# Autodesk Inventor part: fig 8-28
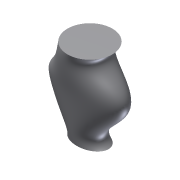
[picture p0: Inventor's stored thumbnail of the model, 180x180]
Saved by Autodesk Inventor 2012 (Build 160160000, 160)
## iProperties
Shininess: 64.0
Length Units: 11269
Angle Units: 11279
Time Units: 11290
Mass Units: 11283
Length Display Precision: 3
Angle Display Precision: 2
Compacted: True
Part Number: fig 8-28
Document SubType Name: Modeling
Created: 2002-12
Designer: deepak
Density: 1 g/cm^3
Material: Default
Density: 0.0
Volumn: 0.0
Area: 0.0
PropertySet Name: Model Information
Control State: 0
Master: False
Checked Out: False
Author: deepak
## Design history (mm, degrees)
sketch "Sketch1"
  geometry: 2 further points; 1 other entity
  constraints: 1 coincident, 3 other
workplane "Work Plane1"
workplane "Work Plane2"
sketch "Sketch3"
  geometry: C1 r 60 at (0, 0); 1 further point
  constraints: 1 centre point, 1 coincident, 1 other
sketch "Sketch4"
  geometry: 8 further points
  constraints: 8 other
sketch "Sketch5"
  geometry: 6 further points
  constraints: 6 other
sketch "Sketch6"
  geometry: 6 further points
  constraints: 6 other
  dimensions: "d20" = 35 distance of point (0, 0) point (-35, 0); "d21" = 0 vertical distance of point (0, 0) point (-35, 0); "d22" = 225 vertical distance of point (0, 0) point (-60, 225); "d23" = 60 horizontal distance of point (0, 0) point (-60, 225); "d24" = 100 horizontal distance of point (0, 0) point (-100, 125); "d25" = 125 vertical distance of point (0, 0) point (-100, 125)
loft "Loft5" dims "d54" = 0, "d55" = 90 deg, "d56" = 0, "d57" = 90 deg, "d58" = 0, "d59" = 90 deg, "d60" = 0, "d61" = 90 deg
body "Solid2"
other parameters: "d5" = 125
